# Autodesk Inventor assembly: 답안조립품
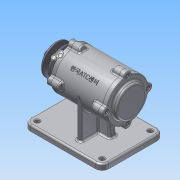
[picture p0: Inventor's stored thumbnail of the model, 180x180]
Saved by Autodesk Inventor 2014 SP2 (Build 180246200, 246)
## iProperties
Created: 2015-12
Part Number: 답안조립품
Document SubType Name: Assembly
Designer: Administrator
Author: Administrator
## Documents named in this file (11)
- C:\Users\Administrator\Desktop\451207v1003\답안조립품.iam
- C:\Users\Administrator\Desktop\451207v1003\1-본체.ipt
- C:\Users\Administrator\Desktop\451207v1003\축.ipt
- C:\Users\Administrator\Desktop\451207v1003\베어링 6204.ipt
- C:\Users\Administrator\Desktop\451207v1003\키(4 x 4 x 12).ipt
- C:\Users\Administrator\Desktop\451207v1003\V-벨트풀리.ipt
- C:\Users\Administrator\Desktop\451207v1003\너트 M12x1.25.ipt
- C:\Users\Administrator\Desktop\451207v1003\커버.ipt
- C:\Users\Administrator\Desktop\451207v1003\커버2.ipt
- C:\Users\Administrator\Desktop\451207v1003\오일실.ipt
- C:\Users\Administrator\Desktop\451207v1003\볼트 M4 x 12.ipt
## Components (7 placed, 6 different names)
1. 1-본체:1
2. KS B 2023 6204 - 20 x 47 x 14:1
3. KS B 2023 6204 - 20 x 47 x 14:2
4. KS B 1311 (I) 4 x 4 x 12:1 — 각도:1, 각도:3
5. V-벨트풀리:1
6. KS B 1012 클래스 1 일반 - 미터 M12x1.25:1 — 각도:3
7. KS B 2804 D D - 20 32 8:1
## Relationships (2: Angle 2)
- 각도:1 [Angle]: KS B 1311 (I) 4 x 4 x 12:1
- 각도:3 [Angle]: KS B 1311 (I) 4 x 4 x 12:1 ↔ KS B 1012 클래스 1 일반 - 미터 M12x1.25:1
